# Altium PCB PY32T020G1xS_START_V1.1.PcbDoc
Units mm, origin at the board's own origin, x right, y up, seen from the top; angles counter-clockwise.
Board outline 98.43 x 90.42 mm, 2 copper layers (Top Layer, Bottom Layer); 76 components, 62 nets, 236 pads, 57 vias.
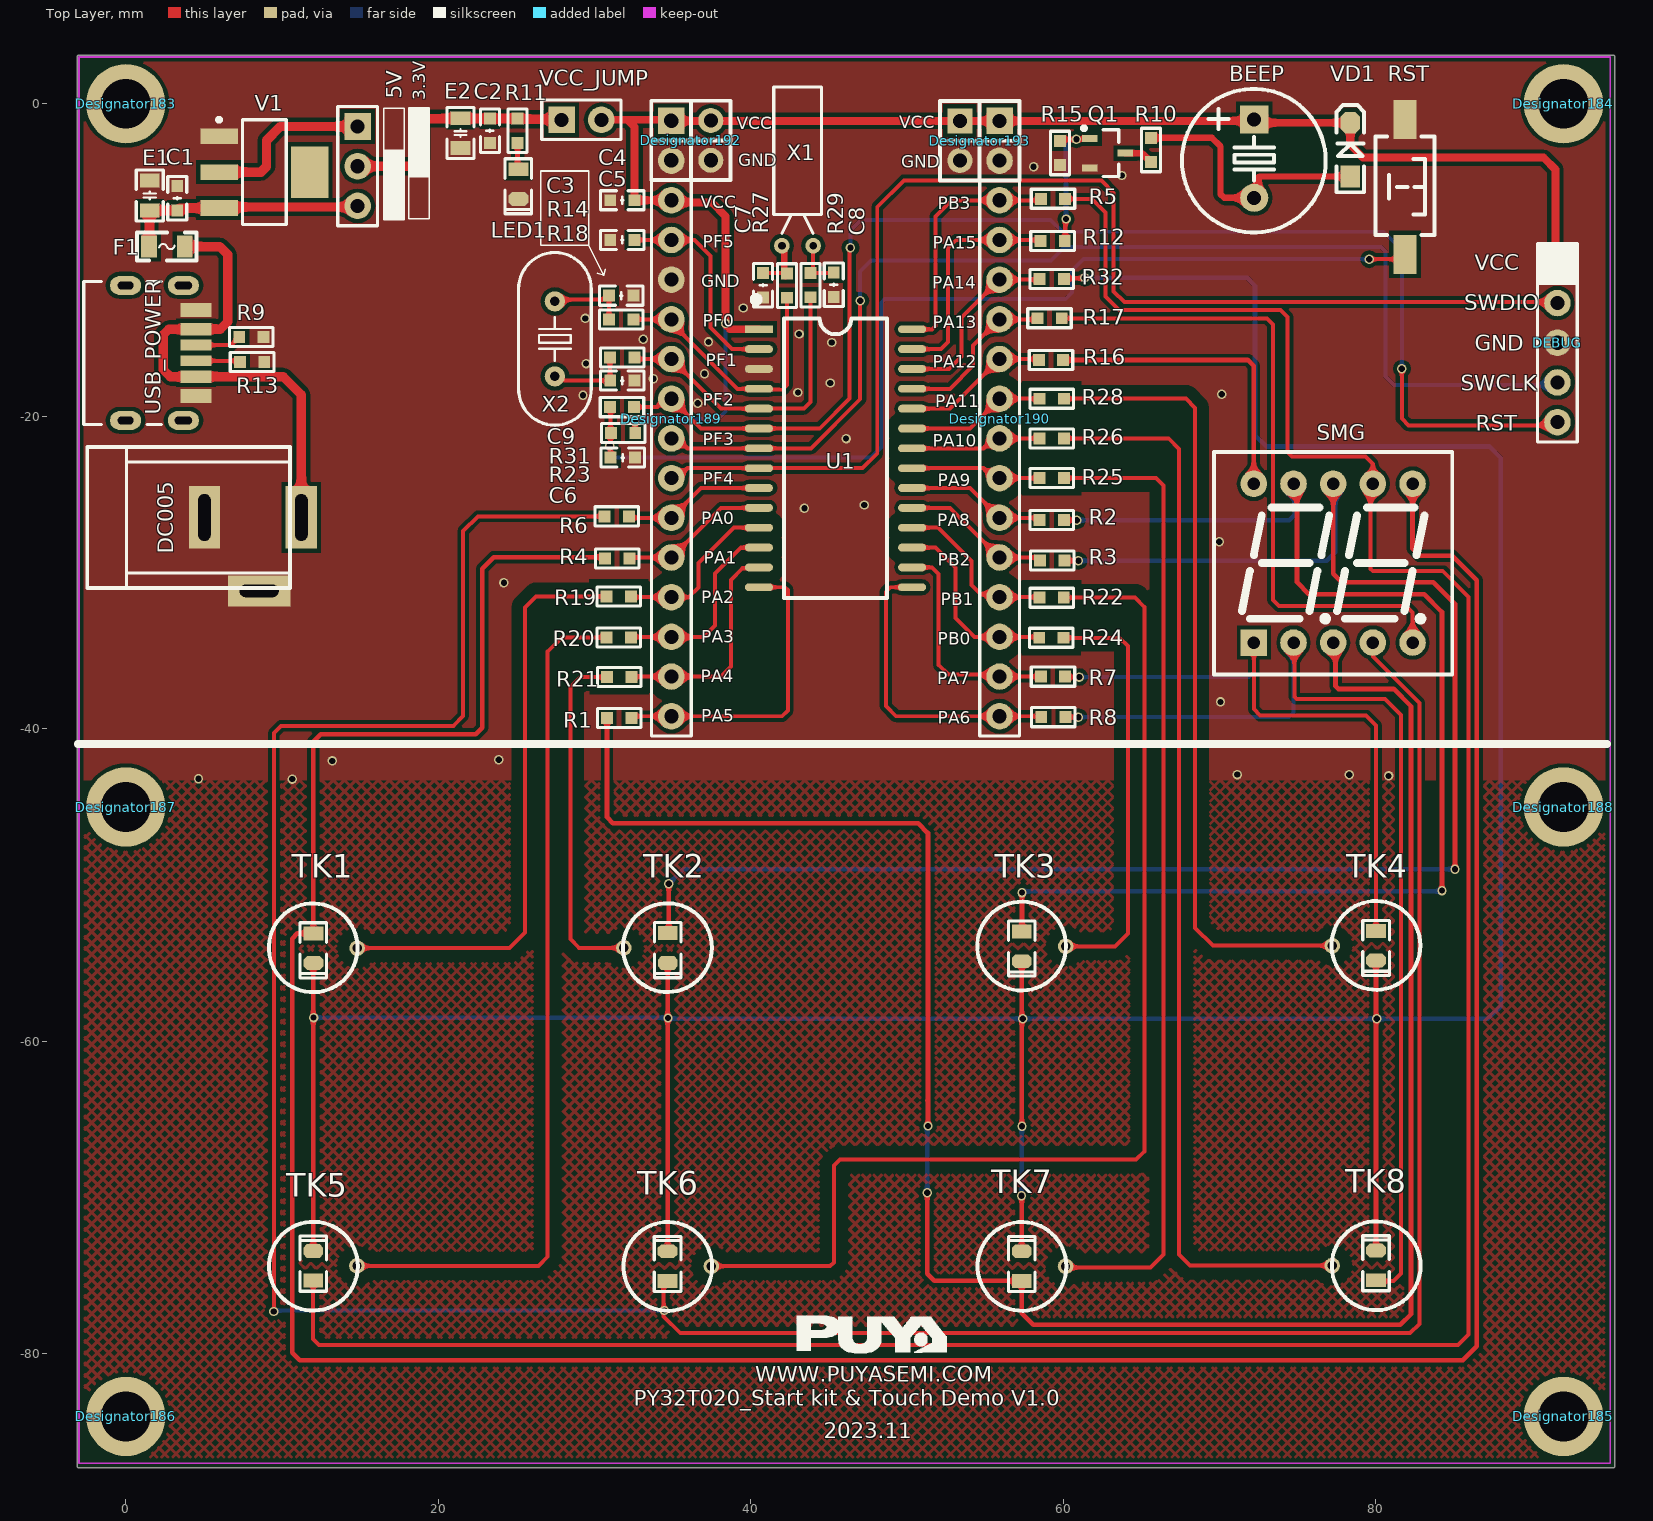
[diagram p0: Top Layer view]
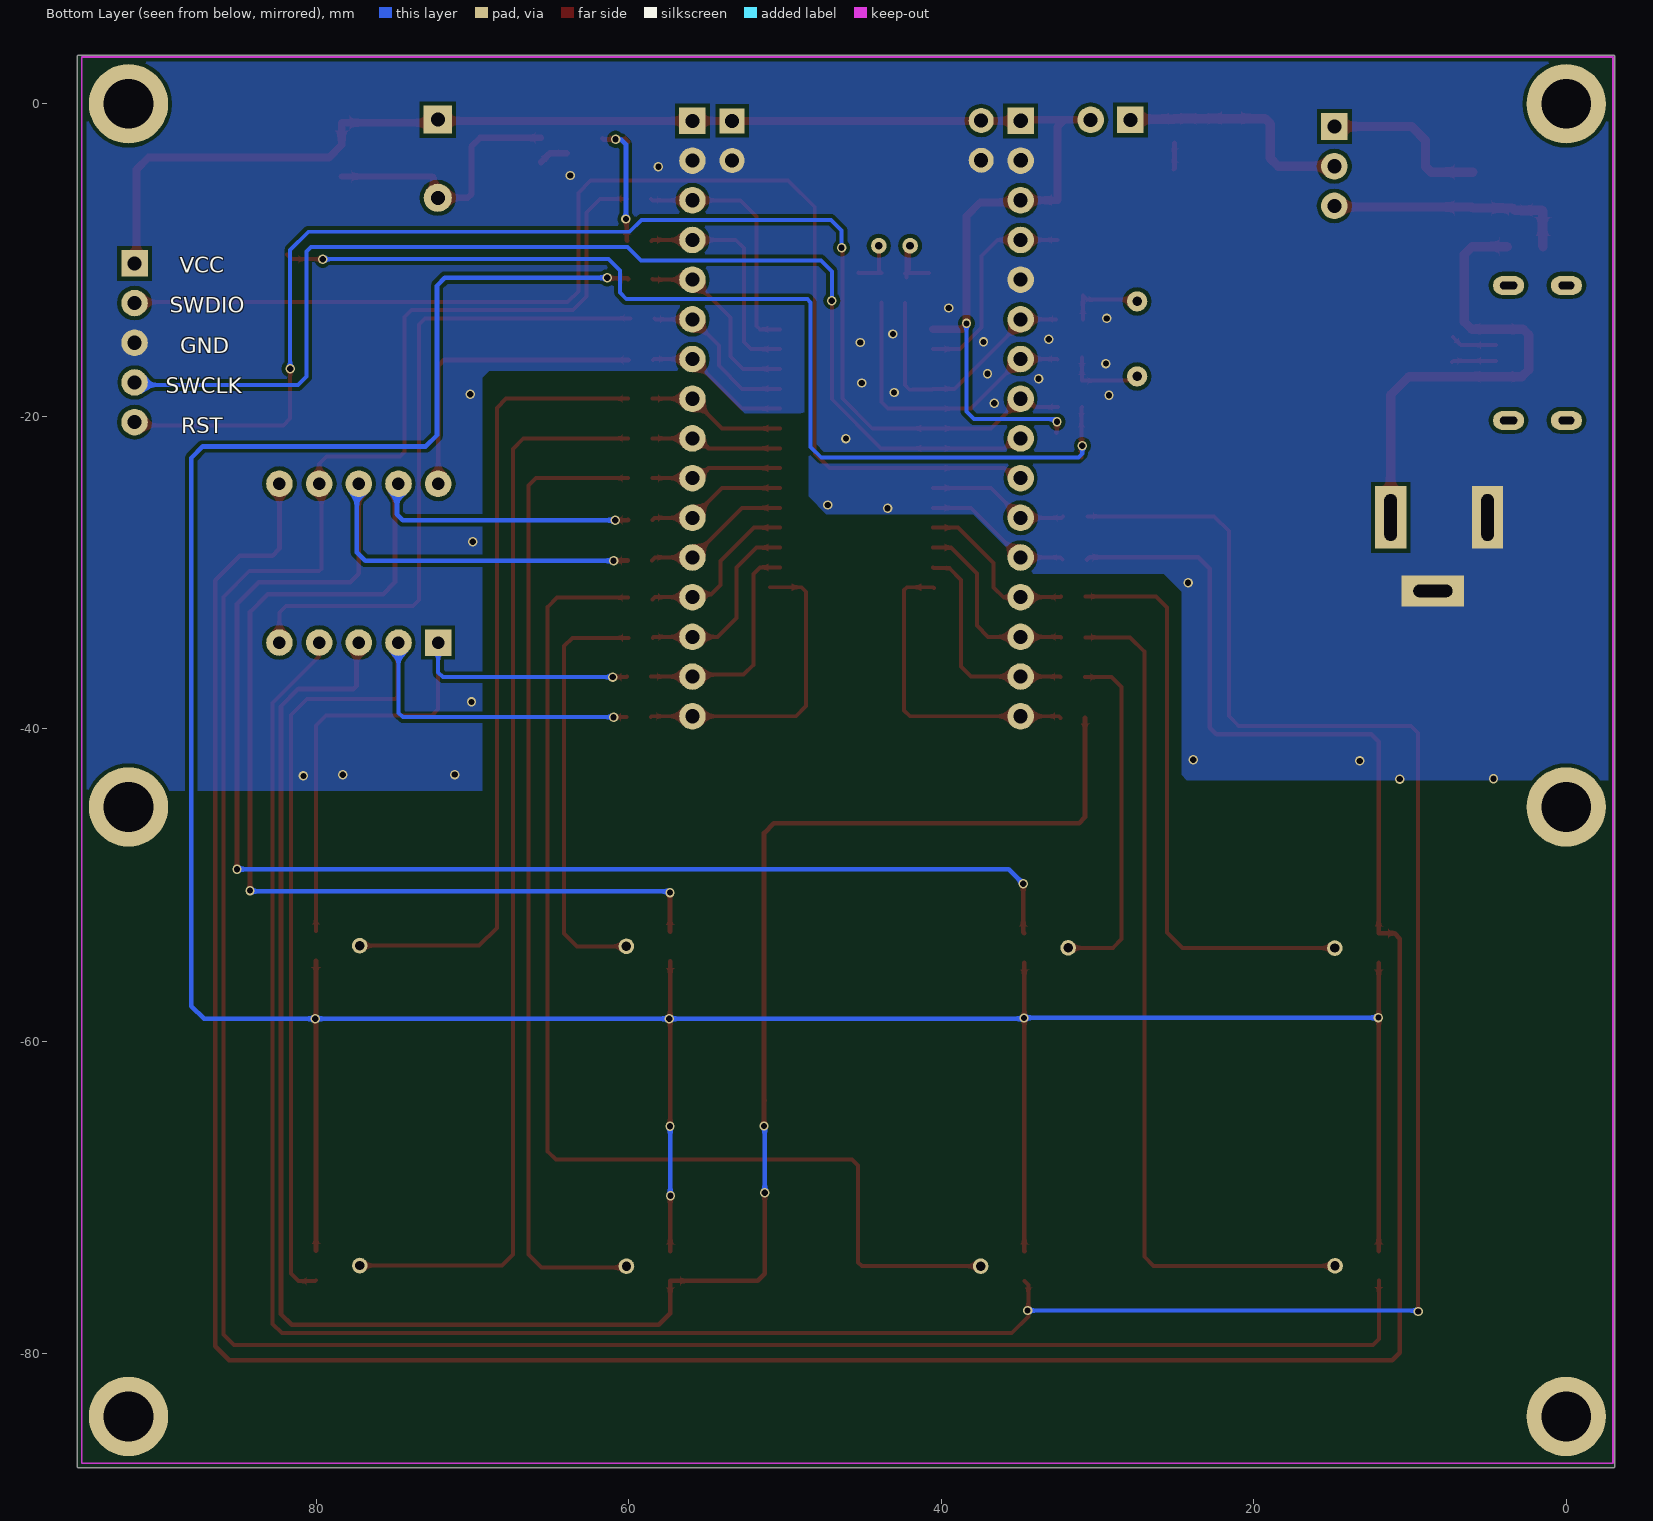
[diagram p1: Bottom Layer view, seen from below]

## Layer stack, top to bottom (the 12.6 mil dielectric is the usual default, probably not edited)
Top Solder: solder mask 0.0102, Solder Resist, Dk 3.5
Top Layer: signal copper 0.0356
Dielectric 1: dielectric 0.32, FR-4, Dk 4.8
Bottom Layer: signal copper 0.0356
Bottom Solder: solder mask 0.0102, Solder Resist, Dk 3.5

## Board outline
-3.11,-87.106 cw(c-2.999,-87.043) -3.127,-87.043 -3.127,3 cw(c-2.999,3) -2.999,3.128 95.172,3.128 cw(c95.172,3) 95.299,3 95.299,-87.17 cw(c95.172,-87.17) 95.172,-87.297 -2.999,-87.297 cw(c-2.999,-87.17)

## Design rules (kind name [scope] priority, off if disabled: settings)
Clearance [InNet('PA2')] p1: gap=0.762 ignorepadtopadclearanceinfootprint=FALSE
Clearance Clearance_10 [InNet('PA3')] p2: gap=0.762 ignorepadtopadclearanceinfootprint=FALSE
Clearance Clearance_9 [InNet('PA4')] p3: gap=0.762 ignorepadtopadclearanceinfootprint=FALSE
Clearance Clearance_15 [InNet('PB0')] p4: gap=0.762 ignorepadtopadclearanceinfootprint=FALSE
Clearance Clearance_14 [InNet('PB1')] p5: gap=0.762 ignorepadtopadclearanceinfootprint=FALSE
Clearance Clearance_13 [InNet('PA9')] p6: gap=0.762 ignorepadtopadclearanceinfootprint=FALSE
Clearance Clearance_12 [InNet('PA10')] p7: gap=0.762 ignorepadtopadclearanceinfootprint=FALSE
Clearance Clearance_11 [InNet('PA11')] p8: gap=0.762 ignorepadtopadclearanceinfootprint=FALSE
Clearance Clearance_8 [InNet('NetR28_2')] p9: gap=0.762 ignorepadtopadclearanceinfootprint=FALSE
Clearance Clearance_7 [InNet('NetR26_2')] p10: gap=0.762 ignorepadtopadclearanceinfootprint=FALSE
Clearance Clearance_6 [InNet('NetR24_2')] p11: gap=0.762 ignorepadtopadclearanceinfootprint=FALSE
Clearance Clearance_17 [InNet('NetR25_2')] p12: gap=0.762 ignorepadtopadclearanceinfootprint=FALSE
Clearance Clearance_5 [InNet('NetR22_2')] p13: gap=0.762 ignorepadtopadclearanceinfootprint=FALSE
Clearance Clearance_4 [InNet('NetR19_2')] p14: gap=0.762 ignorepadtopadclearanceinfootprint=FALSE
Clearance Clearance_16 [InNet('NetR21_2')] p15: gap=0.762 ignorepadtopadclearanceinfootprint=FALSE
Clearance Clearance_3 [InNet('NetR20_2')] p16: gap=0.762 ignorepadtopadclearanceinfootprint=FALSE
Clearance Clearance_1 [All] p17: gap=0.254 ignorepadtopadclearanceinfootprint=FALSE except(0: Arc-Hole Track-Hole SMDPad-Hole THPad-Hole Via-Hole Fill-Hole Poly-Hole Region-Hole Text-Hole)
PlaneConnect [InNet('GND')] p1: planeconnectstyle=Direct reliefexpansion=0.508 reliefentries=4 reliefconductorwidth=0.254 reliefairgap=0.254
PlaneConnect PlaneConnect_1 [All] p2: planeconnectstyle=Relief reliefexpansion=0.508 reliefentries=4 reliefconductorwidth=0.254 reliefairgap=0.254
PolygonConnect PolygonConnect_1 [InNet('GND')] p1: connectstyle=Direct reliefconductorwidth=0.254 reliefentries=4 polygonreliefangle="90 Angle" airgapwidth=0.254
PolygonConnect [All] p2: connectstyle=Relief reliefconductorwidth=0.254 reliefentries=4 polygonreliefangle="90 Angle" airgapwidth=0.254
RoutingVias [All] p1: holewidth=0.711 width=1.27 viastyle="Through Hole" minholewidth=0.711 minwidth=1.27 maxholewidth=0.711 maxwidth=1.27
SolderMaskExpansion [All] p1: expansion=0.102
Width [All] p1: maxlimit=0.8 minlimit=0.254 preferedwidth=0.254
29 further rules are at their usual default settings.

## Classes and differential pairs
component class PY32T020_StartKit_V1.0: 5V BEEP C1 C2 C3 C4 C5 C6 C7 C8 C9 DEBUG E1 E2 F1 LED1 Q1 R1 R2 R3 R4 R5 R6 R7 R8 R9 R10 R11 R12 R13 R14 R15 R16 R17 R18 R19 R20 R21 R22 R23 R24 R25 R26 R28 R31 R32 RST SMG TK1 TK2 TK3 TK4 TK5 TK6 TK7 TK8 U1 USB_POWER V1 VCC_JUMP VD1 X1 X2

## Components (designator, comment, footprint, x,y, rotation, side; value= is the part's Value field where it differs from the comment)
5V "HDR-1X3" HDR2.54-LI-3P 14.833,-3.989 r270 top (schematic designator 5V/3.3V)
BEEP "DC5V" "BEEP 5x9x5.5" 72.21,-3.51 r180 top
C1 "104" "C 0603_L" 3.291,-6.039 r270 top
C2 "104" "C 0603_L" 23.298,-1.724 r90 top
C3 "20PF" "C 0603_L" 31.697,-12.273 r180 top
C4 "104" "C 0603_L" 31.773,-6.169 r0 top
C5 "22NF" "C 0603_L" 31.773,-8.709 r0 top (schematic designator C7)
C6 "104" "C 0603_L" 31.799,-22.636 r180 top
C7 "20PF" "C 0603_L" 40.778,-11.609 r90 top
C8 "20PF" "C 0603_L" 45.3,-11.579 r270 top
C9 "20PF" "C 0603_L" 31.773,-17.708 r0 top
DC005 "Comment" DC-005 5.029,-26.47 r180 top
DEBUG "ISP" ISP_DIP_2.54_5P 91.616,-10.208 r270 top
Designator183 "Comment" "M3 125X200"#1 -0.155,0.148 r180 top
Designator184 "Comment" "M3 125X200"#2 92.073,0.122 r180 top
Designator185 "Comment" "M3 125X200"#3 91.92,-84.104 r180 top
Designator186 "Comment" "M3 125X200"#4 0.337,-83.522 r180 top
Designator187 "Comment" "M3 125X200"#5 -0.022,-45.804 r180 top
Designator188 "Comment" "M3 125X200"#6 91.936,-45.804 r180 top
Designator189 "Comment" HDR2.54-LI-16P 34.913,-20.139 r270 top
Designator190 "Comment" HDR2.54-LI-16P 55.913,-20.139 r270 top
Designator192 "Comment" HDR2.54-LI-2x2P 36.163,-2.339 r270 top
Designator193 "Comment" HDR2.54-LI-2x2P 54.643,-2.359 r270 top
E1 "10uF/10V" "C 0805_L" 1.529,-5.862 r90 top
E2 "10uF/10V" "C 0805_L" 21.416,-1.867 r270 top
F1 "500ma" "FU 0805" 2.626,-9.131 r180 top
LED1 "红色" "LED 0805R" 25.118,-5.135 r270 top
Q1 "SS8050" SOT23-3L 62.837,-3.154 r270 top
R1 "0R" "R 0603_L" 31.57,-39.298 r180 top
R2 "0R" "R 0603_L" 59.256,-26.624 r0 top
R3 "0R" "R 0603_L" 59.281,-29.215 r0 top
R4 "0R" "R 0603_L" 31.443,-29.088 r180 top
R5 "0R" "R 0603_L" 59.332,-6.075 r0 top
R6 "0R" "R 0603_L" 31.418,-26.395 r180 top
R7 "0R" "R 0603_L" 59.332,-36.657 r0 top
R8 "0R" "R 0603_L" 59.358,-39.248 r0 top
R9 "5.1K" "R 0603_L" 8.032,-14.912 r180 top
R10 "200R" "R 0603_L" 65.606,-2.951 r90 top
R11 "1K" "R 0603_L" 25.068,-1.717 r90 top
R12 "1K" "R 0603_L" 59.307,-8.768 r180 top
R13 "5.1K" "R 0603_L" 8.078,-16.521 r180 top
R14 "NC" "R 0603_L" 31.697,-13.797 r180 top
R15 "10K" "R 0603_L" 59.789,-3.144 r90 top
R16 "0R" "R 0603_L" 59.205,-16.388 r180 top
R17 "0R" "R 0603_L" 59.114,-13.721 r180 top
R18 "NC" "R 0603_L" 31.763,-16.235 r180 top
R19 "1K" "R 0603_L" 31.545,-31.526 r180 top
R20 "1K" "R 0603_L" 31.545,-34.142 r180 top
R21 "1K" "R 0603_L" 31.57,-36.682 r180 top
R22 "1K" "R 0603_L" 59.246,-31.602 r0 top
R23 "10K" "R 0603_L" 31.824,-21.061 r0 top
R24 "1K" "R 0603_L" 59.231,-34.168 r0 top
R25 "1K" "R 0603_L" 59.256,-23.949 r0 top
R26 "1K" "R 0603_L" 59.256,-21.409 r0 top
R27 "NC" "R 0603_L" 42.302,-11.629 r270 top
R28 "1K" "R 0603_L" 59.256,-18.869 r0 top
R29 "NC" "R 0603_L" 43.816,-11.599 r270 top
R31 "0R" "R 0603_L" 31.748,-19.41 r180 top
R32 "0R" "R 0603_L" 59.256,-11.206 r180 top
RST "6x6x5" "TSW SMD-3*6*5" 81.862,-5.313 r270 top
SMG "3621A" "SMG 0.36-2P" 77.265,-29.392 r0 top
TK1 "Comment" TLEDL 12.001,-54.023 r0 top
TK2 "Comment" TLEDR 34.663,-54.039 r0 top
TK3 "Comment" TLEDL 57.338,-53.912 r0 top
TK4 "Comment" TLEDR 80.001,-53.896 r0 top
TK5 "Comment" TLEDR 12.001,-74.343 r180 top locked
TK6 "Comment" TLEDR 34.679,-74.359 r180 top locked
TK7 "Comment" TLEDR 57.346,-74.359 r180 top locked
TK8 "Comment" TLEDL 80.001,-74.343 r180 top locked
U1 "PY32T020G16" SOP28_L 45.415,-22.679 r0 top
USB_POWER "USB-C" USB-C/S_C -2.566,-15.94 r270 top
V1 "AMS1117-3V3" SOT223_N 8.865,-4.366 r0 top
VCC_JUMP "HDR-1X2" HDR2.54-LI-2P 29.157,-1.021 r0 top
VD1 "A7" SOD-123 78.357,-2.926 r90 top
X1 "32.768KHZ" OSC-3x8-WI-A 42.984,-9.08 r0 top
X2 "24M" "OSC HC-49S" 27.455,-15.041 r270 top

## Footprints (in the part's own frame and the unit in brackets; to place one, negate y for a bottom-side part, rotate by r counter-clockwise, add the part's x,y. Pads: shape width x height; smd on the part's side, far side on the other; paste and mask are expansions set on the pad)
"BEEP 5x9x5.5" [mm] "5*9*5.5mm(脚距,直径,高度)"
  rect 1.8x1.8 hole 0.9: 1(0,-2.5)
  round 1.8 hole 0.9: 2(0,2.5)
  silkscreen extent -4.58,-4.47 4.62,4.72, body extent -4.5,-4.5 4.5,4.5, height 5.45
"C 0603_L" [mil] "无极性贴片电容"
  rect 30x30 smd: 1(-30.59,0) 2(30.59,0)
  silkscreen extent -55,-24 55,24, body extent -31,-16 31,16, height 32
"C 0805_L" [mil] "无极性贴片电容"
  rect 35x50 smd: 1(-37.4,0) 2(37.4,0)
  silkscreen extent -64,-34 64,34, body extent -39,-24 39,24, height 20
DC-005 [mm] "5.5*2.1mm，DC30V,2.5A"
  rect 2x4 hole 0.8 slot 3 at 90 deg: 1(-6.2,0) 2(0,0)
  rect 4x2 hole 0.8 slot 2.5 at 0 deg: 3(-3.5,4.7)
  silkscreen extent -5.48,-4.5 7.5,4.5, body extent -6.55,-4.5 7.5,4.8, height 11.2
"FU 0805" [mil] "贴片保险丝"
  rect 40x55 smd: 1(-45,0) 2(45,0)
  silkscreen extent -75,-35 75,35, body extent -39,-24 39,24, height 20
HDR2.54-LI-2P [mm] "排针，2脚"
  rect 1.7x1.7 hole 0.9: 1(-1.27,0)
  round 1.7 hole 0.9: 2(1.27,0)
  silkscreen extent -2.54,-1.27 2.54,1.27, body extent -2.54,-1.27 2.54,1.27, height 8.5
HDR2.54-LI-2x2P [mm] "双排排针，2x2脚"
  rect 1.6x1.6 hole 0.9: 1(-1.27,-1.27)
  round 1.6 hole 0.9: 2(-1.27,1.27) 3(1.27,-1.27) 4(1.27,1.27)
  silkscreen extent -2.54,-2.54 2.54,2.54, body extent -2.54,-2.54 2.54,2.54, height 8.5
HDR2.54-LI-3P [mm] "排针，3脚"
  rect 1.7x1.7 hole 0.9: 1(-2.54,0)
  round 1.7 hole 0.9: 2(0,0) 3(2.54,0)
  silkscreen extent -3.81,-1.27 3.81,1.27, body extent -3.81,-1.27 3.81,1.27, height 8.5
HDR2.54-LI-16P [mm] "排针，16脚"
  rect 1.7x1.7 hole 0.9: 1(-19.05,0)
  round 1.7 hole 0.9: 2(-16.51,0) 3(-13.97,0) 4(-11.43,0) 5(-8.89,0) 6(-6.35,0) 7(-3.81,0) 8(-1.27,0) 9(1.27,0) 10(3.81,0) 11(6.35,0) 12(8.89,0) 13(11.43,0) 14(13.97,0) 15(16.51,0) 16(19.05,0)
  silkscreen extent -20.32,-1.27 20.32,1.27, body extent -20.32,-1.27 20.32,1.27, height 8.5
ISP_DIP_2.54_5P [mm] "5P 下载端口"
  rect 1.7x1.7 hole 0.9: 1(0,0)
  round 1.7 hole 0.9: 2(2.54,0) 3(5.08,0) 4(7.62,0) 5(10.16,0)
  silkscreen extent -1.27,-1.27 11.43,1.27
"LED 0805R" [mil] "红色0805LED"
  rect 35x50 smd: 1(-37.41,0)
  oct 35x50 smd: 2(37.4,0)
  silkscreen extent -64,-33 75,33, body extent -39,-25 39,25, height 32
"M3 125X200"#1 [mm] "M3螺丝孔，孔125Mil，焊盘200Mil"
  round 5.08 hole 3.175: 1(-0.155,0.148)
"M3 125X200"#2 [mm] "M3螺丝孔，孔125Mil，焊盘200Mil"
  round 5.08 hole 3.175: 1(0.073,0.122)
"M3 125X200"#3 [mm] "M3螺丝孔，孔125Mil，焊盘200Mil"
  round 5.08 hole 3.175: 1(-0.08,-0.104)
"M3 125X200"#4 [mm] "M3螺丝孔，孔125Mil，焊盘200Mil"
  round 5.08 hole 3.175: 1(0.337,0.478)
"M3 125X200"#5 [mm] "M3螺丝孔，孔125Mil，焊盘200Mil"
  round 5.08 hole 3.175: 1(-0.022,-0.804)
"M3 125X200"#6 [mm] "M3螺丝孔，孔125Mil，焊盘200Mil"
  round 5.08 hole 3.175: 1(-0.064,-0.804)
"OSC HC-49S" [mm]
  round 1.3 hole 0.6: 1(-2.4,0) 2(2.4,0)
  silkscreen extent -5.52,-2.32 5.52,2.33, body extent -5.52,-2.32 5.53,2.33, height 4.13
OSC-3x8-WI-A [mm] "脚距：2mm"
  round 1 hole 0.5: 1(1,0) 2(-1,0)
  silkscreen extent -1.52,0.8 1.52,10.16, body extent -1.5,-0.18 1.5,10, height 3.03
"R 0603_L" [mil] "1/10W贴片电阻"
  rect 30x30 smd: 1(-30.59,0) 2(30.59,0)
  silkscreen extent -55,-24 55,24, body extent -31,-16 32,16, height 16
"SMG 0.36-2P" [mm] "15*14*7.2mm(长宽厚)"
  rect 1.7x1.7 hole 0.8: 1(-5.08,-5.08)
  round 1.7 hole 0.8: 2(-2.54,-5.08) 3(0,-5.08) 4(2.54,-5.08) 5(5.08,-5.08) 6(5.08,5.08) 7(2.54,5.08) 8(0,5.08) 9(-2.54,5.08) 10(-5.08,5.08)
  silkscreen extent -7.62,-7.11 7.62,7.11, body extent -7.5,-7 7.5,7, height 7.2
SOD-123 [mil] "2.7x1.6X1.1mm（长宽高，不包括引脚）"
  rect 55x50 smd: 1(-67.5,0)
  oct 55x50 smd: 2(67.5,0)
  silkscreen extent -108,-35 112,35, body extent -73,-31 73,31, height 48
SOP28_L [mm] "17.9*10.6*2.6mm（长宽高）"
  rect 1.8x0.5 smd: 1(-4.9,8.255)
  oval 1.8x0.5 smd: 2(-4.9,6.985) 3(-4.9,5.715) 4(-4.9,4.445) 5(-4.9,3.175) 6(-4.9,1.905) 7(-4.9,0.635) 8(-4.9,-0.635) 9(-4.9,-1.905) 10(-4.9,-3.175) 11(-4.9,-4.445) 12(-4.9,-5.715) 13(-4.9,-6.985) 14(-4.9,-8.255) 15(4.9,-8.255) 16(4.9,-6.985) 17(4.9,-5.715) 18(4.9,-4.445) 19(4.9,-3.175) 20(4.9,-1.905) 21(4.9,-0.635) 22(4.9,0.635) 23(4.9,1.905) 24(4.9,3.175) 25(4.9,4.445) 26(4.9,5.715) 27(4.9,6.985) 28(4.9,8.255)
  silkscreen extent -5.23,-8.95 3.3,10.31, body extent -5.15,-8.95 5.15,8.95, height 2.7
SOT23-3L [mm] "3x1.3x1mm(长宽高)"
  rect 0.45x1 smd: 1(-0.95,-1.143) 2(0.95,-1.143) 3(0,1.125)
  silkscreen extent -1.72,-1.65 1.5,0.7, body extent -1.5,-1.2 1.5,1.2, height 1.05
SOT223_N [mm] "SOT223, 4-Leads, Body 6.5x3.5mm, Pitch 2.3mm, Lead Span 7mm, IPC Medium Density"
  rect 2.4x1 smd: 1(-2.9,2.3) 2(-2.9,0) 3(-2.9,-2.3)
  rect 2.4x3.3 smd: 4(2.9,0)
  silkscreen extent -3.02,-3.35 1.4,3.47, body extent -1.85,-3.35 1.85,3.35, height 1.7
TLEDL [mm]
  rect 1.27x0.889 smd: 1(0,0.94)
  oct 1.27x0.889 smd: 2(0,-0.96)
  round 1 hole 0.6: 3(2.802,-0.002)
  silkscreen extent -2.85,-2.83 2.83,2.85, body extent -0.63,-1.01 0.63,0.99, height 0.8
TLEDR [mm]
  rect 1.27x0.889 smd: 1(0.011,0.966)
  oct 1.27x0.889 smd: 2(0.011,-0.934)
  round 1 hole 0.6: 3(-2.79,0.024)
  silkscreen extent -2.84,-2.8 2.84,2.88, body extent -0.61,-0.98 0.64,1.02, height 0.8
"TSW SMD-3*6*5" [mm] "3*6*5mm"
  rect 2.5x1.5 smd: 1(-4.318,0) 2(4.318,0)
  silkscreen extent -3.21,-1.9 3.09,1.9, body extent -4.6,-1.75 4.6,1.75, height 5.1
USB-C/S_C [mm] "Type-C 6P母座"
  oval 1.2x2 hole 0.5 slot 1.1 at 90 deg: 0(-4.32,6.25) 0(4.32,6.25)
  oval 1.2x2 hole 0.5 slot 1 at 90 deg: 0(-4.32,2.55) 0(4.32,2.55)
  rect 0.7x2 smd: A5(-0.5,7.05) B5(0.5,7.05)
  rect 0.8x2 smd: A9(1.52,7.05) B9(-1.52,7.05)
  rect 0.9x2 smd: A12(2.75,7.05) B12(-2.75,7.05)
  silkscreen extent -4.57,-0.13 4.57,4.83, body extent -4.47,0 4.48,7.05, height 3.16

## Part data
5V: library part "Header 3", "3P接插件"
BEEP: library part BEEP, "蜂鸣器"
C1 C2 C3 C4 C5 C6 C7 C8 C9: library part C, "无极性贴片电容"
DEBUG: library part ISP_5Pin, "程序下载端口"
E1 E2: library part C-CM, "贴片电解电容"
F1: library part FU, "贴片保险丝"
LED1: library part LED-SMD, "贴片LED"
Q1: library part 8050-DIP, "高频放大-NPN型"
R1 R2 R3 R4 R5 R6 R7 R8 R10 R11 R12 R14 R15 R16 R17 R18 R19 R20 R21 R22 R23 R24 R25 R26 R27 R28 R29 R31 R32: library part R, "贴片电阻"
R9 R13: library part R
RST: library part "TSW DIP-2Pin-6x6", "2脚直插6x6轻触开关"
SMG: "0.36寸2位共阴数码管"
TK1 TK2 TK3 TK4 TK5 TK6 TK7 TK8: library part TLED
USB_POWER: library part USB-C_6P/S, "USB-C_6P型母接口"
V1: library part AMS1117, "三端稳压芯片"
VCC_JUMP: library part "Header 2", "2P接插件"
VD1: library part DIODE
X1 X2: library part XTAL-2P, "2脚无源脚晶振"

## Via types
v1: diameter 0.6, hole 0.4, Top Layer to Bottom Layer, 57 vias

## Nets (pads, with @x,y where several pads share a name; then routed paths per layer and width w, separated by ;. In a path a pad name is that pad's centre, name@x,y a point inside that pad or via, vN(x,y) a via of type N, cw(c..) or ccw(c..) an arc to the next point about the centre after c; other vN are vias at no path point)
CMOD: C5.2 Designator189.4 U1.2 | length 13.5
  Top Layer w0.254: C5.2 Designator189.4 36.388,-8.709 37.412,-9.733 37.412,-14.305 38.801,-15.694 U1.2
COM0: R16.1 SMG.10 | length 19.9
  Top Layer w0.3: R16.1 71.804,-16.388 72.185,-16.769 SMG.10
COM1: R17.1 SMG.5 | length 42.5
  Top Layer w0.254: R17.1 73.023,-13.721 73.416,-14.113 73.416,-31.741 73.81,-32.136 81.938,-32.136 82.345,-32.542 SMG.5
COM_LED: R32.1 TK1.2 TK2.2 TK3.2 TK4.2 TK5.2 TK6.2 TK7.2 TK8.2 | length 223.8
  Top Layer w0.3: TK5.2 11.995,-73.404 11.995,-54.988 TK1.2 ; TK6.2 34.671,-73.422 34.671,-54.975 TK2.2 ; v1(57.321,-69.88) 57.328,-69.887 57.328,-73.418 TK7.2 ; TK3.2 57.337,-65.396 v1@57.376,-65.435 ; R32.1 60.071,-11.168 61.326,-11.168 v1(61.364,-11.13) ; TK8.2 80.006,-73.377 80.006,-54.835 TK4.2
  Bottom Layer w0.3: v1(12.012,-58.475) 12.025,-58.488 34.656,-58.488 34.669,-58.501 v1(34.694,-58.501) 34.745,-58.552 v1(57.402,-58.552) v1(80.059,-58.552) 87.171,-58.552 87.983,-57.739 87.983,-22.661 87.247,-21.925 72.972,-21.925 72.261,-21.214 72.261,-11.638 71.753,-11.13 v1(61.364,-11.13) ; v1(57.321,-69.88) 57.336,-69.865 57.336,-65.45 v1(57.351,-65.435)
GND: C1.1 C2.1 C3.1 C4.1 C5.1 C6.1 C7.1 C8.2 C9.2 DC005.2 DC005.3 DEBUG.3 Designator189.2 Designator189.5 Designator190.2 Designator192.3 Designator192.4 Designator193.3 Designator193.4 E1.2 E2.2 LED1.2 Q1.2 R9.1 R13.1 R15.1 RST.1 U1.3 USB_POWER.A12 USB_POWER.B12 V1.1
  other v1: 10.64,-43.21 4.646,-43.185 80.811,-43.007 78.297,-42.936 71.132,-42.924 13.2,-42.045 23.863,-41.97 70.051,-38.272 24.192,-30.65 69.966,-28.021 43.422,-25.881 47.258,-25.669 46.092,-21.419 36.597,-19.166 29.254,-18.647 70.137,-18.58 43.006,-18.469 45.08,-17.863 33.76,-17.596 37.03,-17.266 29.454,-16.619 45.171,-15.274 37.287,-15.233 33.108,-15.056 43.085,-14.725 29.404,-13.728 39.508,-13.063 63.729,-4.586 58.091,-4.028
Net5V/3.3V_1: 5V.1 V1.2 | length 11.1
  Top Layer w0.6: V1.2 8.648,-4.366 8.999,-4.015 8.999,-2.336 9.886,-1.449 5V.1
Net5V/3.3V_2: 5V.2 C2.2 E2.1 R11.2 VCC_JUMP.1 | length 15.6
  Top Layer w0.6: 5V.2 18.429,-3.989 18.927,-3.491 18.927,-1.276 19.263,-0.94 R11.2 25.108,-0.98 27.847,-0.98 VCC_JUMP.1
NetBEEP_2: BEEP.2 R10.2 VD1.1 | length 17.3
  Top Layer w0.4: R10.2 69.503,-2.174 70.051,-2.722 70.051,-5.775 70.285,-6.01 BEEP.2 72.478,-5.742 72.478,-4.708 72.546,-4.64 VD1.1
NetC3_2: C3.2 R14.2 X2.1 | length 5.1
  Top Layer w0.254: X2.1@27.455,-12.565 27.494,-12.527 30.666,-12.527 C3.2 R14.2
NetC6_2: C6.2 R23.1 R31.2 RST.2 | length 66.4
  Top Layer w0.254: R31.2 31.022,-19.461 C6.2 ; v1(79.572,-9.94) 81.553,-9.94 RST.2
  Bottom Layer w0.254: v1(30.96,-21.874) 30.96,-22.382 31.218,-22.64 47.67,-22.64 48.359,-21.95 48.359,-12.705 48.563,-12.501 60.12,-12.501 60.551,-12.07 60.551,-10.673 61.284,-9.94 v1(79.572,-9.94)
NetC7_2: C7.2 R27.1 X1.2 | length 5.1
  Top Layer w0.254: C7.2 42.204,-10.832 R27.1@42.224,-10.852 ; X1.2 42.048,-9.143 42.048,-10.598 R27.1@42.224,-10.774 ; R27.1@42.224,-11.104 R27.1@42.224,-10.852 ; X1.2@42.224,-9.41 R27.1@42.224,-10.774 ; R27.1 R27.1@42.224,-10.774 ; R27.1@42.224,-10.852 R27.1@42.224,-10.774
NetC8_1: C8.1 R29.1 X1.1 | length 3.3
  Top Layer w0.254: X1.1 43.984,-10.653 R29.1 45.28,-10.822 C8.1
NetC9_1: C9.1 R18.2 X2.2 | length 5.2
  Top Layer w0.254: X2.2@27.455,-17.365 27.738,-17.365 28.081,-17.708 C9.1 30.986,-17.698 R18.2
NetLED1_1: LED1.1 R11.1 | length 1.7
  Top Layer w0.3: R11.1 25.068,-4.134 LED1.1
NetQ1_1: Q1.1 R12.1 R15.2 | length 8.8
  Top Layer w0.3: R15.2@60.018,-2.428 60.167,-2.279 61.619,-2.279 Q1.1 ; R12.1 60.127,-8.724 60.127,-7.414 v1(60.17,-7.371)
  Bottom Layer w0.3: v1(60.17,-7.371) 60.17,-2.595 60.501,-2.265 v1(60.831,-2.265)
NetQ1_3: Q1.3 R10.1 | length 1.9
  Top Layer w0.4: Q1.3 65.032,-3.154 R10.1
NetR9_2: R9.2 USB_POWER.A5 | length 3
  Top Layer w0.254: USB_POWER.A5 6.727,-15.44 R9.2
NetR13_2: R13.2 USB_POWER.B5 | length 2.9
  Top Layer w0.254: USB_POWER.B5 7.22,-16.44 R13.2
NetR19_2: R19.2 TK1.3 | length 37.5
  Top Layer w0.254: TK1.3 24.565,-54.025 25.55,-53.04 25.55,-32.237 26.261,-31.526 R19.2
NetR20_2: R20.2 TK5.3 | length 55.3
  Top Layer w0.254: TK5.3 26.397,-74.367 26.998,-73.766 26.998,-35.057 27.912,-34.142 R20.2
NetR21_2: R21.2 TK2.3 | length 22.4
  Top Layer w0.254: R21.2 29.081,-36.682 28.446,-37.317 28.446,-53.446 29.014,-54.014 TK2.3
NetR22_2: R22.2 TK6.3 | length 74.6
  Top Layer w0.254: TK6.3 45.076,-74.383 45.311,-74.147 45.311,-67.95 45.692,-67.569 64.641,-67.569 65.174,-67.035 65.174,-32.186 64.59,-31.602 R22.2
NetR24_2: R24.2 TK3.3 | length 27.1
  Top Layer w0.254: R24.2 63.599,-34.168 64.133,-34.701 64.133,-53.091 63.31,-53.914 TK3.3
NetR25_2: R25.2 TK7.3 | length 62.4
  Top Layer w0.254: R25.2 65.928,-23.949 66.393,-24.414 66.393,-73.639 65.559,-74.474 60.227,-74.474 TK7.3
NetR26_2: R26.2 TK8.3 | length 69.3
  Top Layer w0.254: R26.2 66.741,-21.409 67.409,-22.077 67.409,-73.639 68.111,-74.341 TK8.3
NetR28_2: R28.2 TK4.3 | length 51.2
  Top Layer w0.254: R28.2 67.833,-18.869 68.425,-19.461 68.425,-52.735 69.562,-53.871 TK4.3
NRST: DEBUG.5 Designator189.8 R31.1 U1.6 | length 83.8
  Top Layer w0.254: R31.1 33.98,-19.41 34.522,-18.869 Designator189.8 36.818,-20.774 U1.6 44.405,-20.774 46.314,-18.865 46.314,-9.26 v1(46.368,-9.206) ; v1(81.659,-16.946) 81.659,-20.147 82.087,-20.575 91.408,-20.575 DEBUG.5
  Bottom Layer w0.254: v1(46.368,-9.206) 46.368,-8.091 47.038,-7.421 59.18,-7.421 59.942,-8.183 80.49,-8.183 81.659,-9.352 v1(81.659,-16.946)
OSCIN: Designator189.6 R14.1 R27.2 U1.4 | length 17
  Top Layer w0.254: R14.1@32.66,-13.789 Designator189.6 34.913,-14.016 39.131,-18.234 U1.4 40.562,-18.281 41.786,-18.281 41.799,-18.295 42.01,-18.295 42.302,-18.003 R27.2@42.302,-12.736
OSCOUT: Designator189.7 R18.1 R29.2 U1.5 | length 19.1
  Top Layer w0.254: R18.1@32.55,-16.362 32.583,-16.329 Designator189.7 38.088,-19.504 U1.5 43.396,-19.504 43.816,-19.084 R29.2@43.816,-12.706
PA0: Designator189.11 R6.1 U1.9 | length 9.1
  Top Layer w0.254: R6.1 32.288,-26.489 Designator189.11 36.818,-24.584 U1.9
PA1: Designator189.12 R4.1 U1.10 | length 9.7
  Top Layer w0.254: R4.1@32.22,-29.164 32.355,-29.029 Designator189.12 38.088,-25.854 U1.10
PA2: Designator189.13 R19.1 U1.11 | length 11
  Top Layer w0.254: R19.1 32.365,-31.569 Designator189.13 36.023,-31.569 36.652,-30.94 36.652,-29.389 38.917,-27.124 U1.11
PA3: Designator189.14 R20.1 U1.12 | length 12.5
  Top Layer w0.254: R20.1 32.355,-34.109 Designator189.14 36.988,-34.109 37.71,-33.387 37.71,-30.041 39.358,-28.394 U1.12
PA4: Designator189.15 R21.1 U1.13 | length 14.3
  Top Layer w0.254: R21.1 32.38,-36.649 Designator189.15 38.08,-36.649 38.726,-36.003 38.726,-30.462 39.477,-29.711 40.468,-29.711 U1.13
PA5: Designator189.16 R1.1 U1.14 | length 19.9
  Top Layer w0.254: R1.1 32.456,-39.189 Designator189.16 41.992,-39.189 42.365,-38.816 42.365,-31.12 42.179,-30.934 U1.14 U1.14@40.468,-30.981
PA6: Designator190.16 R8.1 U1.15 | length 20
  Top Layer w0.254: U1.15@50.965,-30.934 U1.15 48.926,-30.934 48.639,-31.221 48.639,-38.536 49.291,-39.189 Designator190.16 58.522,-39.189 R8.1
PA7: Designator190.15 R7.1 U1.16 | length 14.5
  Top Layer w0.254: U1.16 51.603,-29.664 52.017,-30.078 52.017,-35.895 52.652,-36.53 55.794,-36.53 Designator190.15 58.547,-36.649 R7.1
PA8: Designator190.11 R2.1 U1.20 | length 9
  Top Layer w0.254: U1.20 54.008,-24.584 Designator190.11 58.344,-26.489 R2.1
PA9: Designator190.10 R25.1 U1.21 | length 8.4
  Top Layer w0.254: U1.21 54.887,-23.314 55.522,-23.949 Designator190.10 R25.1
PA10: Designator190.9 R26.1 U1.22 | length 8.4
  Top Layer w0.254: U1.22 54.887,-22.044 55.522,-21.409 Designator190.9 R26.1
PA11: Designator190.8 R28.1 U1.23 | length 9
  Top Layer w0.254: U1.23 54.008,-20.774 Designator190.8 R28.1
PA12: Designator190.7 R16.2 U1.24 | length 9.5
  Top Layer w0.254: U1.24 52.738,-19.504 Designator190.7 58.37,-16.329 R16.2
PA13: Designator190.6 R17.2 U1.25 | length 10.6
  Top Layer w0.254: U1.25 52.736,-18.234 54.227,-16.743 54.227,-15.475 Designator190.6 58.269,-13.789 R17.2
PA14: Designator190.5 R32.2 U1.26 | length 12
  Top Layer w0.254: U1.26 52.685,-16.964 53.49,-16.159 53.49,-13.672 Designator190.5 58.436,-11.249 R32.2
PA15: Designator190.4 R12.2 U1.27 | length 14.7
  Top Layer w0.254: U1.27 52.173,-15.694 52.627,-15.24 52.627,-9.225 53.142,-8.709 Designator190.4 58.471,-8.709 R12.2
PB0: Designator190.14 R24.1 U1.17 | length 12.4
  Top Layer w0.254: U1.17 51.817,-28.394 53.096,-29.674 53.096,-32.91 54.295,-34.109 Designator190.14 58.395,-34.109 R24.1
PB1: Designator190.13 R22.1 U1.18 | length 11
  Top Layer w0.254: U1.18 51.984,-27.124 54.112,-29.253 54.112,-30.802 54.682,-31.372 55.716,-31.372 Designator190.13 58.308,-31.569 R22.1@58.469,-31.729
PB2: Designator190.12 R3.1 U1.19 | length 9.6
  Top Layer w0.254: U1.19 52.738,-25.854 Designator190.12 58.319,-29.029 R3.1
PB3: Designator190.3 R5.1 U1.28 | length 15.8
  Top Layer w0.254: U1.28 51.596,-14.424 51.814,-14.206 51.814,-7.193 52.838,-6.169 Designator190.3 58.461,-6.169 R5.1
SEGA: R1.2 SMG.3 TK7.1 | length 136.5
  Top Layer w0.3: R1.2 30.793,-45.659 31.164,-46.029 50.696,-46.029 51.331,-46.664 51.331,-63.809 ; v1(51.28,-69.677) 51.28,-74.858 51.747,-75.325 TK7.1 57.335,-77.407 58.062,-78.135 81.557,-78.135 82.243,-77.449 82.243,-38.551 81.136,-37.444 77.593,-37.444 77.417,-37.268 77.417,-34.625 SMG.3 ; 51.306,-63.784 51.331,-63.809 ; v1(51.331,-65.41) 51.331,-63.809
  Bottom Layer w0.3: v1(51.28,-69.677) 51.28,-65.46 v1(51.331,-65.41)
SEGB: R2.2 SMG.9 TK3.1 | length 80.6
  Top Layer w0.3: TK3.1 57.351,-52.958 v1(57.351,-50.474) ; R2.2 60.046,-26.637 60.843,-26.637 v1(60.856,-26.649) ; SMG.9 74.953,-24.541 74.953,-30.612 75.715,-31.374 83.081,-31.374 84.224,-32.517 v1(84.224,-50.347)
  Bottom Layer w0.3: v1@57.351,-50.398 84.173,-50.398 v1(84.224,-50.347) ; v1(60.856,-26.649) 74.445,-26.649 74.826,-26.268 74.826,-24.414 SMG.9
SEGC: R3.2 SMG.8 TK2.1 | length 107.2
  Top Layer w0.3: TK2.1 34.745,-53.002 v1(34.745,-49.916) ; R3.2 60.071,-29.227 60.945,-29.227 v1(60.958,-29.24) ; SMG.8 77.265,-30.078 77.798,-30.612 83.665,-30.612 85.062,-32.009 v1(85.062,-48.976)
  Bottom Layer w0.3: v1(34.745,-49.916) 35.685,-48.976 v1(85.062,-48.976) ; v1(60.958,-29.24) 76.858,-29.24 77.392,-28.707 77.392,-24.439 SMG.8
SEGD: R4.2 SMG.6 TK1.1 | length 204.4
  Top Layer w0.3: R4.2@30.666,-29.164 30.514,-29.011 23.544,-29.011 22.807,-29.748 22.807,-39.933 22.401,-40.34 12.469,-40.34 12,-40.809 TK1.1 10.979,-53.083 10.64,-53.421 10.64,-79.913 11.123,-80.396 85.57,-80.396 86.457,-79.509 86.457,-30.482 84.885,-28.91 82.776,-28.91 82.345,-28.478 SMG.6
SEGDP: R8.2 SMG.2 TK8.1 | length 67.6
  Top Layer w0.254: R8.2 v1(60.958,-39.248) ; SMG.2 74.775,-34.523 74.775,-37.93 74.924,-38.079 80.592,-38.079 81.608,-39.095 81.608,-74.858 81.125,-75.341 80.059,-75.341 TK8.1
  Bottom Layer w0.254: v1(60.958,-39.248) 74.445,-39.248 74.725,-38.968 SMG.2
SEGE: R5.2 SMG.7 TK5.1 | length 174
  Top Layer w0.254: TK5.1 11.989,-79.052 12.368,-79.43 85.24,-79.43 85.926,-78.745 85.926,-31.551 84.275,-29.9 79.801,-29.9 79.652,-29.752 79.652,-24.465 SMG.7 79.805,-23.042 79.322,-22.56 74.623,-22.56 74.344,-22.28 74.344,-13.644 73.889,-13.19 63.549,-13.19 62.685,-12.326 62.685,-6.939 61.821,-6.075 R5.2
SEGF: R6.2 SMG.4 TK6.1 | length 192.2
  Top Layer w0.254: v1@9.447,-77.297 v1(9.459,-77.284) 9.472,-77.271 9.472,-40.264 9.929,-39.806 20.953,-39.806 21.588,-39.171 21.588,-27.335 22.528,-26.395 R6.2 ; TK6.1 34.415,-75.578 34.415,-77.602 35.479,-78.666 82.195,-78.666 82.774,-78.087 82.774,-38.331 79.805,-35.361 SMG.4
  Bottom Layer w0.254: v1(9.459,-77.284) 9.523,-77.221 v1(34.466,-77.221)
SEGG: R7.2 SMG.1 TK4.1 | length 39.8
  Top Layer w0.254: R7.2 60.135,-36.682 v1(61.009,-36.682) ; SMG.1 72.185,-38.74 72.591,-39.146 79.373,-39.146 80.012,-39.785 TK4.1
  Bottom Layer w0.254: v1(61.009,-36.682) 71.88,-36.682 72.185,-36.377 SMG.1
SWCLK: DEBUG.4 Designator189.9 U1.7 | length 75.5
  Top Layer w0.254: Designator189.9 35.304,-21.409 35.939,-22.044 U1.7 43.853,-22.044 46.995,-18.902 v1(46.995,-12.598)
  Bottom Layer w0.254: v1(46.995,-12.598) 46.995,-10.716 47.699,-10.012 59.205,-10.012 60.069,-9.149 80.313,-9.149 80.617,-9.453 80.617,-17.454 81.151,-17.988 91.455,-17.988 DEBUG.4
SWDIO: DEBUG.2 Designator189.10 U1.8 | length 80.8
  Top Layer w0.254: Designator189.10 35.304,-23.949 35.939,-23.314 U1.8 47.15,-23.314 48.087,-22.377 48.087,-6.605 49.785,-4.907 62.431,-4.907 63.218,-5.694 63.218,-11.993 63.907,-12.682 91.55,-12.682 DEBUG.2
V5V: 5V.3 C1.2 E1.1 F1.2 V1.3 | length 15.8
  Top Layer w0.6: F1.2 1.506,-9.108 1.506,-6.835 1.527,-6.814 3.289,-6.814 C1.2 3.44,-6.666 V1.3 6.034,-6.598 14.764,-6.598 5V.3
VBUS: DC005.1 F1.1 USB_POWER.A9 USB_POWER.B9 | length 31.3
  Top Layer w0.6: F1.1 6.012,-9.131 6.521,-9.641 6.521,-13.94 6.041,-14.42 USB_POWER.B9 2.748,-14.42 2.397,-14.772 2.397,-17.009 2.848,-17.46 USB_POWER.A9 10.076,-17.46 11.229,-18.613 DC005.1
VCC: BEEP.1 C4.2 DEBUG.1 Designator189.1 Designator189.3 Designator190.1 Designator192.1 Designator192.2 Designator193.1 Designator193.2 R23.2 U1.1 VCC_JUMP.2 VD1.2 | length 102.5
  Top Layer w0.254: v1(32.586,-20.35) 32.586,-20.924 32.662,-21 R23.2
  Top Layer w0.5: VCC_JUMP.2 32.099,-1.021 ; U1.1 38.67,-14.424 38.377,-14.131 v1(38.377,-14.051) 38.377,-7.193 37.488,-6.304 35.048,-6.304 Designator189.3 C4.2 32.55,-1.472 32.099,-1.021 ; BEEP.1@72.019,-0.819 71.75,-1.089 Designator193.2 Designator189.1 34.845,-1.021 32.099,-1.021 ; BEEP.1 72.411,-1.211 VD1.2 78.357,-2.621 79.174,-3.438 90.731,-3.438 91.489,-4.196 91.489,-10.081 DEBUG.1
  Bottom Layer w0.254: v1(32.586,-20.35) 32.764,-20.172 37.895,-20.172 38.377,-19.69 v1(38.377,-14.051) v1@38.403,-14.025
pads on no net: Designator183.1 Designator184.1 Designator185.1 Designator186.1 Designator187.1 Designator188.1 USB_POWER.0 V1.4

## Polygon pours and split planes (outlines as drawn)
GND on Top Layer "Top Layer-GND" (solid, remove dead copper, pour order 6): -2.999,3 -2.999,-43.29 95.001,-43.29 95.001,3
GND on Top Layer "Top Layer-GND 1" (hatched 45Degree grid 0.508 track 0.203, remove dead copper, pour order 0): -2.999,-86.974 -2.999,-42.88 95.146,-42.88 95.146,-87.33
GND on Bottom Layer "Bottom Layer-GND" (solid, remove dead copper, pour order 10): -3.064,-43.272 24.273,-43.272 24.611,-42.934 24.611,-31.218 25.757,-30.072 34.18,-30.072 34.18,-30.017 37.946,-26.252 47.351,-26.252 48.479,-25.124 48.479,-20.157 48.861,-19.775 48.88,-19.794 52.572,-19.794 55.301,-17.065 68.907,-17.065 69.363,-17.521 69.363,-43.971 94.978,-43.971 95.001,-43.994 95.001,3 -2.999,3

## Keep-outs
Keep-Out Layer:
  lines w0.1: -2.999,-87 -2.999,3 95.001,3 95.001,-87 -2.999,-87

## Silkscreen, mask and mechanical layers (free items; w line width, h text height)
Top Overlay:
  drawing of 465 lines, arcs and shapes, not listed
  text "3.3V" at 19.144,0.225 h0.8 r90
  text "VCC" at 49.487,-1.57 h0.8
  text "VCC" at 39.099,-1.62 h0.8
  text "GND" at 39.188,-3.984 h0.8
  text "GND" at 49.617,-4.097 h0.8
  text "VCC" at 36.806,-6.685 h0.8
  text "PB3" at 51.971,-6.748 h0.8
  text "PF5" at 36.929,-9.213 h0.8
  text "PA15" at 51.636,-9.282 h0.8
  text "VCC" at 86.309,-10.647 h1
  text "GND" at 36.825,-11.741 h0.8
  text "PA14" at 51.617,-11.815 h0.8
  text "SWDIO" at 85.656,-13.219 h1
  text "PF0" at 36.929,-14.268 h0.8
  text "PA13" at 51.636,-14.349 h0.8
  text "GND" at 86.332,-15.791 h1
  text "PF1" at 37.101,-16.796 h0.8
  text "PA12" at 51.636,-16.882 h0.8
  text "SWCLK" at 85.416,-18.362 h1
  text "PF2" at 36.929,-19.323 h0.8
  text "PA11" at 51.807,-19.416 h0.8
  text "RST" at 86.385,-20.934 h1
  text "PF3" at 36.929,-21.851 h0.8
  text "PA10" at 51.636,-21.95 h0.8
  text "PF4" at 36.91,-24.379 h0.8
  text "PA9" at 51.948,-24.483 h0.8
  text "PA0" at 36.825,-26.906 h0.8
  text "PA8" at 51.929,-27.017 h0.8
  text "PA1" at 36.996,-29.434 h0.8
  text "PB2" at 51.971,-29.55 h0.8
  text "PA2" at 36.825,-31.961 h0.8
  text "PB1" at 52.142,-32.084 h0.8
  text "PA3" at 36.825,-34.489 h0.8
  text "PB0" at 51.971,-34.617 h0.8
  text "PA4" at 36.806,-37.016 h0.8
  text "PA7" at 51.929,-37.151 h0.8
  text "PA5" at 36.825,-39.544 h0.8
  text "PA6" at 51.948,-39.684 h0.8
  text "WWW.PUYASEMI.COM" at 40.263,-81.775 h1.02
  text "PY32T020_Start kit & Touch Demo V1.0" at 32.5,-83.327 h1.02
  text "2023.11" at 44.653,-85.382 h1.02
Bottom Overlay:
  text "VCC" at 88.718,-10.8 h1
  text "SWDIO" at 89.371,-13.371 h1
  text "GND" at 88.695,-15.943 h1
  text "SWCLK" at 89.611,-18.515 h1
  text "RST" at 88.642,-21.087 h1

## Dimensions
-2.999,-87 to 95.001,-87 on Top Overlay
-2.999,3 to -2.999,-87 on Top Overlay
